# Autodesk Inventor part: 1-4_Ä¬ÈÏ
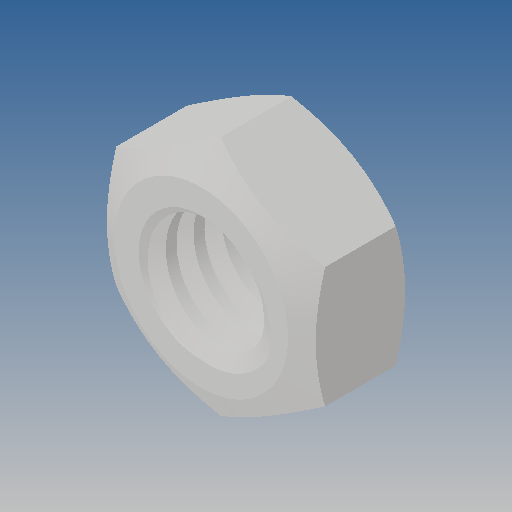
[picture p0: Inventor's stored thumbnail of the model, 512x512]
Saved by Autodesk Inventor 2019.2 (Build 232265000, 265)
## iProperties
Created: 2010-06
Part Number: 1-4_Ä¬ÈÏ
Material: Ogólny
Document SubType Name: Modeling
Designer: CADENGINEERING4
Density: 1 g/cm^3
Appearance: Domyślna
Author: CADENGINEERING4
Revision Number: ÈÎºÎ
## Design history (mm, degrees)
feature "NONE"
node "Bryła1"
